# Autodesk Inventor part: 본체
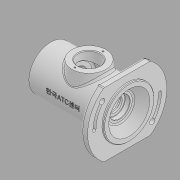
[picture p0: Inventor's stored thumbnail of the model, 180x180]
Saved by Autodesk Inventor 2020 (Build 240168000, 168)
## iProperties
Created: 2022-05
Part Number: 본체
Material: 일반
Document SubType Name: Modeling
Designer: User
Density: 1 g/cm^3
Appearance: 기본값
Author: User
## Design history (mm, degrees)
sketch "스케치1"
  geometry: L1 (0, 0)-(-102, 0); L2 (-102, 0)-(-102, 32); L3 (-102, 32)-(0, 32); L4 (0, 32)-(0, 0); L5 (0, 32)-(0, 37); L6 (0, 37)-(13, 37); L7 (13, 37)-(13, 0); L8 (13, 0)-(0, 0)
  constraints: 16 end point, 3 perpendicular, 2 parallel, 1 collinear, 1 horizontal, 1 vertical
  dimensions: "d1" = 64 diameter of L3 L1; "d4" = 102 distance of L2.end L3.end; "d5" = 74 diameter of L6 L8; "d6" = 13 distance of L5.end L6.end
revolve "회전1" sketch "스케치1" stored, may be unused: angle "d7" = 90 deg
node "작업 평면1"
sketch "스케치2" dims "d11" = 96
  geometry: L1 (-33.985, 47)-(-33.985, -47); L2 (33.985, 47)-(33.985, -47); L3 (33.985, 47)-(-33.985, 47); L4 (-33.985, -47)-(33.985, -47); L5 (0, 0)-(36.77, 30.854); A1 r 58 centre (0, 0) between (-33.985, 47) and (-33.985, -47); A2 r 58 centre (0, 0) between (-33.985, 47) and (-33.985, -47); A3 r 58 centre (0, 0) between (33.985, -47) and (33.985, 47); 2 further points
  constraints: 10 end point, 8 point on circle, 3 centre point, 2 coincident, 2 concentric, 2 horizontal, 2 vertical, 1 horizontal alignment, 1 midpoint, 1 parallel, 3 other
  dimensions: "d9" = 116 diameter of A1; "d10" = 94 distance of L1.start L1.end; "d12" = 40 deg angle of L4 L5
extrude "돌출1" join sketch "스케치2" distance "d14" = 10; taper "d15" = 0 deg
node "작업 평면2"
sketch "스케치4"
  geometry: L1 (102, 32)-(102, -32) reference; C1 r 25 at (46, 0); 2 further points
  constraints: 1 centre point, 1 horizontal alignment, 1 midpoint
  dimensions: "d27" = 50 diameter of C1; "d28" = 56 distance of C1.centre point (102, 0)
extrude "돌출2" join sketch "스케치4" stored distance "d29" = 10; taper "d30" = 5 deg
sketch "스케치5"
  geometry: L1 (-102, -32)-(-102, 32) reference; L2 (13, -37)-(13, 37) reference; L3 (-102, 0)-(13, 0); L4 (-102, 0)-(-102, 22.5); L5 (-102, 22.5)-(-94, 22.5); L6 (-94, 22.5)-(-94, 24); L7 (-94, 24)-(-91, 24); L8 (-91, 24)-(-91, 22.5); L9 (-91, 22.5)-(-80, 22.5); L10 (-80, 22.5)-(-80, 17.5); L11 (-80, 17.5)-(-77.75, 17.5); L12 (-77.75, 17.5)-(-77.75, 18.5); L13 (-77.75, 18.5)-(-76, 18.5); L14 (-76, 18.5)-(-76, 17.5); L15 (-76, 17.5)-(-65, 17.5); L16 (-65, 17.5)-(-65, 27); L17 (-65, 27)-(-27, 27); L18 (-27, 27)-(-27, 17.5); L19 (-27, 17.5)-(-16, 17.5); L20 (-16, 17.5)-(-16, 15); L21 (-16, 15)-(-11, 15); L22 (-11, 15)-(-11, 11); L23 (-11, 11)-(-8.3, 11); L24 (-8.3, 11)-(-8.3, 15); L25 (-8.3, 15)-(-1, 15); L26 (-1, 15)-(-1, 20); L27 (-1, 20)-(13, 30); L28 (13, 0)-(13, 30); 1 further point
  constraints: 52 end point, 19 perpendicular, 6 point on line, 2 midpoint, 1 collinear, 1 horizontal
  dimensions: "d31" = 45 diameter of L5 L3; "d32" = 48 diameter of L7 L3; "d33" = 8 distance of L4.end L5.end; "d34" = 22 distance between parallel lines of L10 L1; "d35" = 3 distance of L6.end L7.end; "d36" = 45 diameter of L9 L3; "d37" = 4 distance between parallel lines of L14 L10; "d39" = 37 diameter of L13 L3; "d40" = 11 distance between parallel lines of L16 L14; "d41" = 35 diameter of L11 L3; "d42" = 54 diameter of L17 L3; "d43" = 38 distance between parallel lines of L18 L16; "d44" = 11 distance of L18.end L19.end; "d45" = 5 distance of L20.end L21.end; "d46" = 30 diameter of L21 L3; "d47" = 22 diameter of L23 L3; "d48" = 30 diameter of L25 L3; "d49" = 40 diameter of L26.end L3; "d50" = 60 diameter of L27.end L3; "d51" = 14 distance from line of L2 L26.end; "d52" = 7.3 distance of L24.end L25.end; "d102" = 1.75 distance of L12.end L13.end
revolve "회전2" sketch "스케치5" stored, may be unused: angle "d53" = 90 deg
sketch "스케치6"
  geometry: C1 r 25 at (0, 0) reference; 2 further points
  constraints: 1 coincident
hole "구멍2" sketch "스케치6" at (0, 0) diameter "d54" = 32; stored, may be unused: countersink angle "d58" = 90 deg, drill point angle "d60" = 118 deg; dims "d55" = 6, "d56" = 8, "d57" = 4.4, "d59" = 8
feature "스레드1" dims "d61" = 8, "d62" = 0
node "작업 평면3"
sketch "스케치8"
  geometry: L1 (0, 0)-(-48, 0); L2 (0, 0)-(-36.77, -30.854); L3 (0, 0)-(36.77, 30.854); A1 r 48 centre (0, 0) between (-48, 0) and (-36.77, -30.854); A2 r 48 centre (0, 0) between (-48, 0) and (-36.77, -30.854); A3 r 52 centre (0, 0) between (-52, 0) and (-39.834, -33.425); A4 r 44 centre (0, 0) between (-44, 0) and (-33.706, -28.283); A5 r 4 centre (-48, 0) between (-44, 0) and (-52, 0); A6 r 4 centre (-36.77, -30.854) between (-39.834, -33.425) and (-33.706, -28.283); A7 r 45.75 centre (0, 0) between (-45.75, 0) and (-35.047, -29.408); A8 r 2.25 centre (-48, 0) between (-45.75, 0) and (-50.25, 0); A9 r 50.25 centre (0, 0) between (-50.25, 0) and (-38.494, -32.3); A10 r 2.25 centre (-36.77, -30.854) between (-38.494, -32.3) and (-35.047, -29.408); 3 further points
  constraints: 21 point on circle, 10 centre point, 6 end point, 4 tangent, 3 coincident, 1 horizontal, 1 point on line, 6 other
  dimensions: "d74" = 96 diameter of A1; "d76" = 40 deg angle of L3 L1; "d77" = 40 deg angle of L1 L2; "d80" = 4 radius of A5; "d81" = 4.5 radial gap between concentric circles of A9 A7
extrude "돌출3" cut sketch "스케치8" extent not by distance; stored distance "d82" = 4.4; taper "d83" = 0 deg
extrude "돌출4" cut sketch "스케치8" extent not by distance; stored distance "d84" = 4.4; taper "d85" = 0 deg
extrude "돌출5" cut sketch "스케치8" extent not by distance; stored distance "d86" = 4.4; taper "d87" = 0 deg
sketch "스케치9"
  geometry: L1 (0, 20.5)-(0, -20.5); C1 r 25 at (0, 0) reference; A1 r 20.5 centre (0, 0) between (0, 20.5) and (0, -20.5); 3 further points
  constraints: 3 coincident, 2 end point, 2 point on circle, 1 centre point, 1 midpoint, 1 vertical
  dimensions: "d91" = 41 diameter of A1
hole "구멍4" sketch "스케치9" at (0, 20.5), (0, -20.5) diameter "d92" = 2.459; stored, may be unused: countersink angle "d96" = 90 deg, drill point angle "d98" = 118 deg; dims "d93" = 6, "d94" = 8, "d95" = 4.4, "d97" = 8
chamfer "모따기1" distance "d99" = 0.7; stored, may be unused: second distance "d100" = 2, angle "d101" = 30 deg
fillet "모깎기1" dims "d103" = 3
fillet "모깎기2" dims "d104" = 0.6, "d105" = 0.5
chamfer "모따기2" distance "d106" = 1; stored, may be unused: second distance "d107" = 2, angle "d108" = 30 deg
fillet "모깎기3" dims "d109" = 3
fillet "모깎기4" dims "d110" = 3
node "작업 평면4"
sketch "스케치10"
  geometry: L1 (-28.15, 14.158)-(26.15, 14.158); L2 (26.15, 14.158)-(26.15, -14.158); L3 (26.15, -14.158)-(-28.15, -14.158); L4 (-28.15, -14.158)-(-28.15, 14.158); L5 (-28.15, 14.158)-(26.15, -14.158); L6 (61, -46.4)-(61, 46.4) reference; 3 further points
  constraints: 2 end point, 2 midpoint, 1 horizontal alignment, 2 other
  dimensions: "d111" = 62 distance from line of L6 point (-1, 0)
feature "엠보싱1" sketch "스케치10" dims "d1" = 64, "d4" = 102, "d5" = 74, "d6" = 13, "d9" = 116, "d10" = 94, "d11" = 96, "d12" = 40 deg, "d112" = 0.5, "d113" = 0
chamfer "모따기3" distance "d114" = 1; stored, may be unused: second distance "d115" = 2, angle "d116" = 30 deg
node "솔리드1"
pattern_circular "원형 패턴1" dims angle "d89" = 360 deg
feature "A9D066F2-1C7D-4E18-AEED-F7BC21143FA4" dims "d61" = 8, "d62" = 0
other parameters: "d8" = -3, "d26" = 38, "d73" = -4.4
